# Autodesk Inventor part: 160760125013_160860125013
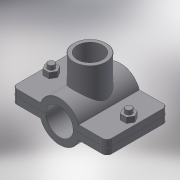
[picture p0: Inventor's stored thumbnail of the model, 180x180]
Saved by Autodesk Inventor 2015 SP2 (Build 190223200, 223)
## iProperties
Created: 2017-05
Part Number: 160760125013_160860125013
Material: Generic
Description: PLASSON SADDLE 125-1.1/4"
Document SubType Name: Modeling
Designer: KIM
Density: 1 g/cm^3
Appearance: Default
Author: KIM
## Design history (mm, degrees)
derived "16076.ipt"
feature "Solid1::16076.ipt"
feature "Solid2::16076.ipt"
tag "TaggingFeature1"
body "Solid1"
other parameters: "d0" = 137.5, "d1" = 184, "d2" = 62.5, "d3" = 125, "d4" = 124, "d5" = 0, "d6" = 9.2, "d7" = 184, "d8" = 0.1, "d10" = 0, "d11" = 1.25, "d14" = 50.6376, "d20" = 1.25, "d23" = 1.25, "d36" = 13, "d37" = 10.4, "d38" = 70.5, "d39" = 0, "d40" = 3, "d41" = 5, "d42" = 0, "d43" = 8, "d44" = 3, "d45" = 0, "d46" = 1.25, "d51" = 98, "d52" = 38.952, "d53" = 25, "d54" = 0, "d55" = 32, "d57" = 0, "d58" = 135, "d60" = 0, "d62" = 13, "d63" = 10.4, "d66" = 103.2, "d_" = 125, "B_" = 32, "G_" = 38.952, "A_" = 98, "L_" = 184, "L_1" = 124, "l_2" = 25
